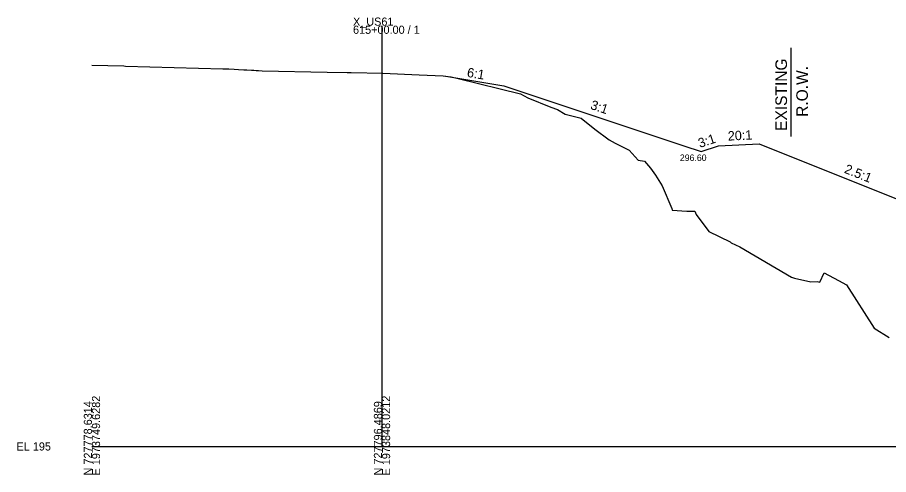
# Model space of a CAD drawing. Extents: x -26 to 1604, y -13 to 9623.
# Drawn here: x -25.7 to 274.6, y 7490.3 to 7647.8 of the extents above; entities that cross this region are included whole.
import ezdxf

# ---------------------------------------------------------------- set-up
doc = ezdxf.new("R2010")
doc.units = 0
for name, color, linetype in [('Draft_XS_Grid', 7, 'Continuous'), ('DTM_X_GROUND', 7, 'Continuous'), ('SLOPE_STAKES_FILL', 7, 'Continuous'), ('XS_CELL', 7, 'Continuous'), ('XS_P_GROUND', 7, 'Continuous'), ('XS_P_TX_DCH', 7, 'Continuous'), ('XS_P_TX_FS_BS', 7, 'Continuous'), ('XS_X_ROW', 7, 'Continuous')]:
    doc.layers.add(name, color=color, linetype=linetype)

msp = doc.modelspace()

# ---------------------------------------------------------------- linework, layer by layer
at = {"layer": 'DTM_X_GROUND'}
msp.add_lwpolyline([(0, 7631.41), (11.04, 7631.12), (11.58, 7631.1), (45.07, 7630.17), (46.29, 7630.12), (47.17, 7630.08), (49.02, 7629.99), (50.51, 7629.93), (52.42, 7629.84), (53, 7629.79), (53.37, 7629.77), (55.06, 7629.68), (55.79, 7629.63), (56.61, 7629.59), (57.43, 7629.53), (58.63, 7629.47), (81.05, 7628.97), (88.03, 7628.89), (88.2, 7628.88), (89.32, 7628.84), (100.27, 7628.67), (112.77, 7628.11), (121.09, 7627.73), (123.57, 7627.38), (123.8, 7627.34), (126.3, 7626.74), (147.78, 7621.52), (150.3, 7620.12), (158.15, 7616.89), (160.5, 7616.11), (163.17, 7614.47), (168.64, 7613.14), (168.67, 7613.12), (168.69, 7613.11), (168.71, 7613.11), (173.43, 7609.34), (178.27, 7605.66), (180.44, 7604.47), (185.17, 7602.05), (188.35, 7598.63), (190.54, 7598.33), (192.58, 7595.9), (194.32, 7593.49), (196.58, 7589.85), (199.9, 7581.98), (200.08, 7581.4), (205.08, 7581.08), (207.82, 7581.06), (208.33, 7579.89), (212.62, 7574.09), (220, 7570.55), (220.35, 7570.16), (223.38, 7568.73), (241.2, 7558.38), (242.19, 7557.94), (247.85, 7556.69), (250.06, 7556.84), (250.97, 7556.63), (252.48, 7559.88), (257.39, 7557.23), (260.17, 7555.73), (269.72, 7540.77), (274.89, 7537.54)], dxfattribs=at)
at = {"layer": 'XS_CELL'}
for p, q in [((100, 7500), (100, 7645)), ((0, 7500), (100, 7500)), ((100, 7500), (600, 7500))]:
    msp.add_line(p, q, dxfattribs=at)
at = {"layer": 'XS_P_GROUND'}
for points in [[(122, 7627.6), (142, 7624.27)], [(142, 7624.27), (204, 7603.6), (210, 7601.6), (216, 7603.6), (230, 7604.3), (294, 7578.7), (300, 7576.3), (306, 7578.7), (320, 7579.4), (384, 7553.8), (390, 7551.4), (396, 7553.8), (410, 7554.5), (466.14, 7532.04)]]:
    msp.add_lwpolyline(points, dxfattribs=at)
at = {"layer": 'XS_X_ROW'}
msp.add_line((241, 7637.35), (241, 7606.81), dxfattribs=at)

# ---------------------------------------------------------------- texts
at = {"layer": 'Draft_XS_Grid'}
msp.add_text('-', height=0.0001, dxfattribs=at).set_placement((0, 7500))
at = {"layer": 'SLOPE_STAKES_FILL'}
for p in [(141.96, 7624.21), (203.96, 7603.54), (209.96, 7601.54), (215.96, 7603.54), (229.96, 7604.24)]:
    msp.add_text('X', height=0.12, dxfattribs=at).set_placement(p)
at = {"layer": 'XS_CELL'}
for s, p in [('X_US61', (90, 7645)), ('615+00.00 / 1', (90, 7642.2)), ('EL 195', (-26, 7498.6))]:
    msp.add_text(s, height=2.8, dxfattribs=at).set_placement(p)
for s, p in [('N 727778.6314', (0, 7490)), ('E 1973749.6282', (2.8, 7490)), ('N 727796.4869', (100, 7490)), ('E 1973848.0212', (102.8, 7490))]:
    msp.add_text(s, height=2.8, rotation=90, dxfattribs=at).set_placement(p)
at = {"layer": 'XS_P_GROUND'}
msp.add_text('X', height=0.12, dxfattribs=at).set_placement((121.96, 7627.54))
at = {"layer": 'XS_P_TX_DCH'}
msp.add_text('296.60', height=2.25, dxfattribs=at).set_placement((202.69, 7598.36))
at = {"layer": 'XS_P_TX_FS_BS'}
for s, rotation, p in [('6:1', 350.5377, (129.13, 7627.39)), ('3:1', 341.5651, (171.61, 7616.37)), ('20:1', 2.8624, (219.3, 7605.37)), ('3:1', 18.4349, (209.61, 7602.85)), ('2.5:1', 338.1986, (259.12, 7594.38))]:
    msp.add_text(s, height=3.24, rotation=rotation, dxfattribs=at).set_placement(p)
at = {"layer": 'XS_X_ROW'}
for s, p in [('EXISTING', (239.63, 7608.74)), ('R.O.W.', (246.83, 7613.58))]:
    msp.add_text(s, height=4, rotation=90, dxfattribs=at).set_placement(p)

doc.saveas('drawing.dxf')
